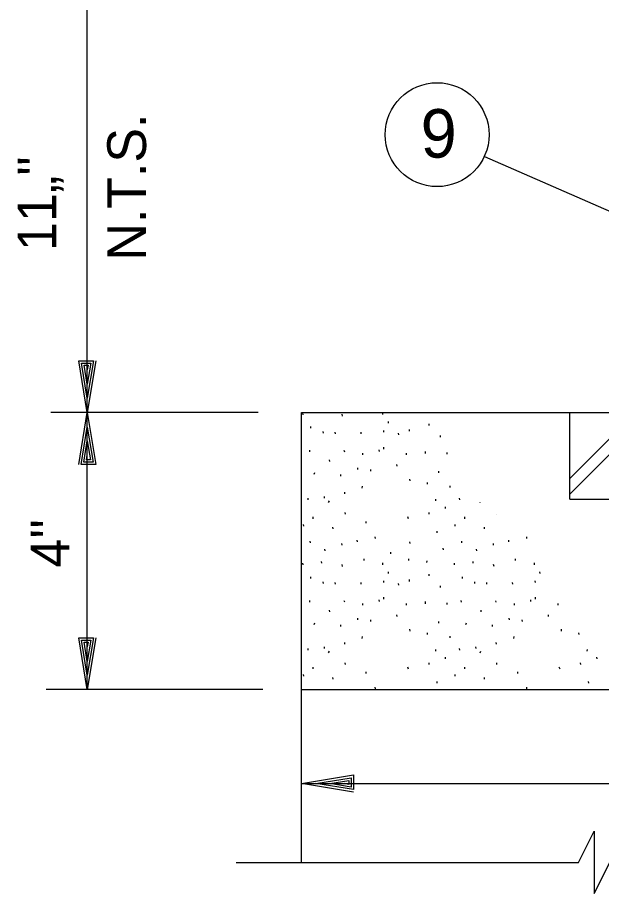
# Model space of a CAD drawing. Extents: x -0.2 to 13.5, y -0.2 to 9.5.
# Drawn here: x 10.065 to 10.768, y 3.258 to 4.312 of the extents above; entities that cross this region are included whole.
import ezdxf

# ---------------------------------------------------------------- set-up
doc = ezdxf.new("R2010")
doc.units = 0
for name, color, linetype in [('Level 13', 7, 'Continuous'), ('Level 2', 7, 'Continuous'), ('Level 3', 7, 'Continuous')]:
    doc.layers.add(name, color=color, linetype=linetype)

msp = doc.modelspace()

# ---------------------------------------------------------------- linework, layer by layer
at = {"layer": 'Level 13'}
msp.add_lwpolyline([(10.74, 3.2959), (10.7587, 3.3334), (10.7587, 3.2585), (10.7774, 3.2959)], dxfattribs=at)
at = {"layer": 'Level 2'}
for p, q in [((10.1487, 3.8371), (10.1487, 4.3787)), ((10.1487, 3.5037), (10.1487, 3.8371)), ((10.4066, 3.2959), (10.4066, 3.8371)), ((10.4066, 3.8371), (10.9376, 3.8371)), ((10.7295, 3.7329), (10.7295, 3.8371)), ((10.7295, 3.7329), (11.3337, 3.7329)), ((10.4066, 3.5037), (11.3337, 3.5037)), ((10.3278, 3.2959), (10.74, 3.2959))]:
    msp.add_line(p, q, dxfattribs=at)
for points in [[(10.7295, 3.7388), (10.8278, 3.8371)], [(10.7295, 3.7576), (10.8089, 3.8371)]]:
    msp.add_lwpolyline(points, dxfattribs=at)
at = {"layer": 'Level 3'}
for p, q in [((10.6266, 4.1453), (10.9022, 4.0249)), ((10.1487, 3.8544), (10.1487, 3.8544)), ((10.3544, 3.8371), (10.1047, 3.8371)), ((10.1487, 3.8371), (10.1487, 3.8371)), ((10.1487, 3.8371), (10.1487, 3.8371)), ((10.4084, 3.8345), (10.4082, 3.8366)), ((10.456, 3.8327), (10.4553, 3.8352)), ((10.5113, 3.8243), (10.5111, 3.8263)), ((10.1487, 3.8197), (10.1487, 3.8197)), ((10.4179, 3.8182), (10.4178, 3.8203)), ((10.5056, 3.8134), (10.5054, 3.8155)), ((10.5364, 3.8148), (10.5363, 3.8168)), ((10.5602, 3.8216), (10.5601, 3.8236)), ((10.4329, 3.8121), (10.4327, 3.8141)), ((10.4472, 3.8114), (10.447, 3.8134)), ((10.4784, 3.8114), (10.4782, 3.8134)), ((10.5235, 3.8101), (10.5234, 3.8121)), ((10.5738, 3.8073), (10.5737, 3.8094)), ((10.5056, 3.7932), (10.5056, 3.7956)), ((10.4166, 3.7897), (10.4164, 3.7917)), ((10.4585, 3.7896), (10.4578, 3.7913)), ((10.4804, 3.7863), (10.4803, 3.7883)), ((10.5002, 3.7903), (10.5, 3.7924)), ((10.533, 3.7863), (10.5329, 3.7883)), ((10.5557, 3.7878), (10.5557, 3.7903)), ((10.5819, 3.7869), (10.5818, 3.789)), ((10.4404, 3.7781), (10.4402, 3.7801)), ((10.5215, 3.7727), (10.5213, 3.7747)), ((10.4217, 3.7628), (10.4226, 3.7648)), ((10.4539, 3.7604), (10.4538, 3.7625)), ((10.4743, 3.7686), (10.4742, 3.7706)), ((10.4899, 3.7666), (10.4898, 3.7686)), ((10.5718, 3.7645), (10.5716, 3.7666)), ((10.5371, 3.755), (10.5369, 3.7571)), ((10.5582, 3.7509), (10.558, 3.753)), ((10.4587, 3.7394), (10.4585, 3.7414)), ((10.4795, 3.7461), (10.4799, 3.7485)), ((10.5854, 3.7468), (10.5852, 3.7489)), ((10.4145, 3.7319), (10.4144, 3.7339)), ((10.4342, 3.7339), (10.4341, 3.736)), ((10.4389, 3.7288), (10.4402, 3.7308)), ((10.5681, 3.7308), (10.5682, 3.7327)), ((10.5969, 3.7319), (10.5967, 3.7339)), ((10.5799, 3.7217), (10.5797, 3.7237)), ((10.4207, 3.7094), (10.4205, 3.7115)), ((10.4594, 3.7149), (10.4592, 3.7169)), ((10.5354, 3.7093), (10.5343, 3.7115)), ((10.5602, 3.7149), (10.5601, 3.7169)), ((10.603, 3.7094), (10.6029, 3.7115)), ((10.4091, 3.7006), (10.4089, 3.7026)), ((10.4444, 3.6972), (10.4443, 3.6993)), ((10.4845, 3.704), (10.4844, 3.7061)), ((10.5915, 3.7006), (10.5913, 3.7026)), ((10.6268, 3.6972), (10.6267, 3.6993)), ((10.5697, 3.6924), (10.5696, 3.6945)), ((10.4172, 3.6802), (10.4171, 3.6823)), ((10.4553, 3.6775), (10.4552, 3.6796)), ((10.4737, 3.6816), (10.4735, 3.6836)), ((10.4954, 3.6856), (10.4952, 3.6877)), ((10.5371, 3.6796), (10.5369, 3.6816)), ((10.5996, 3.6802), (10.5994, 3.6823)), ((10.6377, 3.6775), (10.6375, 3.6796)), ((10.656, 3.6816), (10.6559, 3.6836)), ((10.6778, 3.6856), (10.6776, 3.6877)), ((10.4349, 3.6707), (10.4347, 3.6728)), ((10.514, 3.6673), (10.5139, 3.6693)), ((10.5772, 3.6721), (10.577, 3.6741)), ((10.6173, 3.6707), (10.6171, 3.6728)), ((10.4309, 3.6558), (10.4307, 3.6578)), ((10.4818, 3.6591), (10.4817, 3.6612)), ((10.5357, 3.6591), (10.5356, 3.6612)), ((10.5572, 3.6568), (10.5576, 3.6587)), ((10.6132, 3.6558), (10.6131, 3.6578)), ((10.6642, 3.6591), (10.664, 3.6612)), ((10.4084, 3.6537), (10.4082, 3.6558)), ((10.456, 3.6519), (10.4553, 3.6544)), ((10.5045, 3.6539), (10.5045, 3.6564)), ((10.5908, 3.6537), (10.5906, 3.6558)), ((10.6384, 3.6519), (10.6377, 3.6544)), ((10.6869, 3.6539), (10.6869, 3.6564)), ((10.4179, 3.6374), (10.4178, 3.6395)), ((10.5113, 3.6435), (10.5111, 3.6456)), ((10.5364, 3.634), (10.5363, 3.6361)), ((10.5602, 3.6408), (10.5601, 3.6428)), ((10.6003, 3.6374), (10.6002, 3.6395)), ((10.6937, 3.6435), (10.6935, 3.6456)), ((10.4329, 3.6313), (10.4327, 3.6333)), ((10.4472, 3.6306), (10.447, 3.6326)), ((10.4784, 3.6306), (10.4782, 3.6326)), ((10.5056, 3.6326), (10.5054, 3.6347)), ((10.5235, 3.6293), (10.5234, 3.6313)), ((10.5738, 3.6266), (10.5737, 3.6286)), ((10.6152, 3.6313), (10.6151, 3.6333)), ((10.6295, 3.6306), (10.6294, 3.6326)), ((10.6608, 3.6306), (10.6606, 3.6326)), ((10.6879, 3.6326), (10.6878, 3.6347)), ((10.5056, 3.6124), (10.5056, 3.6148)), ((10.6879, 3.6124), (10.6879, 3.6148)), ((10.4166, 3.6089), (10.4164, 3.6109)), ((10.4585, 3.6088), (10.4578, 3.6106)), ((10.4804, 3.6055), (10.4803, 3.6075)), ((10.5002, 3.6096), (10.5, 3.6116)), ((10.533, 3.6055), (10.5329, 3.6075)), ((10.5557, 3.6071), (10.5557, 3.6096)), ((10.5819, 3.6061), (10.5818, 3.6082)), ((10.5989, 3.6089), (10.5988, 3.6109)), ((10.6409, 3.6088), (10.6402, 3.6106)), ((10.6628, 3.6055), (10.6627, 3.6075)), ((10.6825, 3.6096), (10.6824, 3.6116)), ((10.7154, 3.6055), (10.7152, 3.6075)), ((10.4404, 3.5973), (10.4402, 3.5993)), ((10.5215, 3.5919), (10.5213, 3.5939)), ((10.6227, 3.5973), (10.6226, 3.5993)), ((10.7039, 3.5919), (10.7037, 3.5939)), ((10.4217, 3.5821), (10.4226, 3.584)), ((10.4743, 3.5878), (10.4742, 3.5898)), ((10.4899, 3.5858), (10.4898, 3.5878)), ((10.5718, 3.5837), (10.5716, 3.5858)), ((10.6041, 3.5821), (10.605, 3.584)), ((10.6567, 3.5878), (10.6565, 3.5898)), ((10.6723, 3.5858), (10.6722, 3.5878)), ((10.4539, 3.5796), (10.4538, 3.5817)), ((10.5371, 3.5742), (10.5369, 3.5763)), ((10.6363, 3.5796), (10.6362, 3.5817)), ((10.7195, 3.5742), (10.7193, 3.5763)), ((10.4795, 3.5653), (10.4799, 3.5677)), ((10.5582, 3.5701), (10.558, 3.5722)), ((10.5854, 3.5661), (10.5852, 3.5681)), ((10.6619, 3.5653), (10.6623, 3.5677)), ((10.7406, 3.5701), (10.7404, 3.5722)), ((10.4145, 3.5511), (10.4144, 3.5531)), ((10.4342, 3.5531), (10.4341, 3.5552)), ((10.4587, 3.5586), (10.4585, 3.5606)), ((10.5681, 3.5501), (10.5682, 3.5519)), ((10.5969, 3.5511), (10.5967, 3.5531)), ((10.6166, 3.5531), (10.6164, 3.5552)), ((10.6411, 3.5586), (10.6409, 3.5606)), ((10.7504, 3.5501), (10.7506, 3.5519)), ((10.4389, 3.548), (10.4402, 3.5501)), ((10.5799, 3.5409), (10.5797, 3.5429)), ((10.6213, 3.548), (10.6225, 3.5501)), ((10.7623, 3.5409), (10.7621, 3.5429)), ((10.4207, 3.5286), (10.4205, 3.5307)), ((10.4594, 3.5341), (10.4592, 3.5361)), ((10.5354, 3.5285), (10.5343, 3.5307)), ((10.5602, 3.5341), (10.5601, 3.5361)), ((10.603, 3.5286), (10.6029, 3.5307)), ((10.6417, 3.5341), (10.6416, 3.5361)), ((10.7178, 3.5285), (10.7167, 3.5307)), ((10.7426, 3.5341), (10.7424, 3.5361)), ((10.1487, 3.5211), (10.1487, 3.5211)), ((10.4091, 3.5198), (10.4089, 3.5218)), ((10.4845, 3.5232), (10.4844, 3.5253)), ((10.5915, 3.5198), (10.5913, 3.5218)), ((10.6669, 3.5232), (10.6667, 3.5253)), ((10.4444, 3.5164), (10.4443, 3.5185)), ((10.5697, 3.5116), (10.5696, 3.5137)), ((10.6268, 3.5164), (10.6267, 3.5185)), ((10.7521, 3.5116), (10.7519, 3.5137)), ((10.3598, 3.5037), (10.0991, 3.5037)), ((10.1487, 3.5037), (10.1487, 3.5037)), ((10.4954, 3.5048), (10.4952, 3.5069)), ((10.6778, 3.5048), (10.6776, 3.5069)), ((10.4066, 3.3908), (12.0732, 3.3908)), ((10.4066, 3.3908), (10.4066, 3.3908)), ((10.4239, 3.3908), (10.4239, 3.3908))]:
    msp.add_line(p, q, dxfattribs=at)
for points in [[(10.1591, 3.8994), (10.1487, 3.8371), (10.1384, 3.8994), (10.1561, 3.8994), (10.1487, 3.8544), (10.1417, 3.8967), (10.1531, 3.8967), (10.1487, 3.8711), (10.1451, 3.8941), (10.1497, 3.8941), (10.1487, 3.8884)], [(10.1384, 3.7747), (10.1487, 3.8371), (10.1591, 3.7747), (10.1414, 3.7747), (10.1487, 3.8197), (10.1557, 3.7774), (10.1444, 3.7774), (10.1487, 3.8031), (10.1524, 3.7801), (10.1477, 3.7801), (10.1487, 3.7857)], [(10.4309, 3.8366), (10.4309, 3.8368)], [(10.5045, 3.8347), (10.5045, 3.8359)], [(10.6213, 3.7288), (10.6215, 3.7291)], [(10.6417, 3.7149), (10.6417, 3.715)], [(10.1591, 3.5661), (10.1487, 3.5037), (10.1384, 3.5661), (10.1561, 3.5661), (10.1487, 3.5211), (10.1417, 3.5634), (10.1531, 3.5634), (10.1487, 3.5377), (10.1451, 3.5607), (10.1497, 3.5607), (10.1487, 3.5551)], [(10.4689, 3.3804), (10.4066, 3.3908), (10.4689, 3.4011), (10.4689, 3.3834), (10.4239, 3.3908), (10.4662, 3.3978), (10.4662, 3.3864), (10.4406, 3.3908), (10.4636, 3.3944), (10.4636, 3.3898), (10.4579, 3.3908)]]:
    msp.add_lwpolyline(points, dxfattribs=at)
msp.add_circle((10.5697, 4.1714), 0.0625, dxfattribs=at)

# ---------------------------------------------------------------- texts
msp.add_text('9', height=0.0583, dxfattribs=at).set_placement((10.5499, 4.1438))
for s, p in [('N.T.S.', (10.2194, 4.0199)), ("11„''", (10.1114, 4.0316)), ("4''", (10.1272, 3.6506))]:
    msp.add_text(s, height=0.04667, rotation=90, dxfattribs=at).set_placement(p)

doc.saveas('drawing.dxf')
